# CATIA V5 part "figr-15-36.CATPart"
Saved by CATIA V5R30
Part number: Part1
Bounding box of the stored display mesh (mm): x -63.331 to 107.433, y -39.139 to 39.139, z 0 to 70.926
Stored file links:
  D:\PROJECTS\CATIA V56R 2020\Resources\Parts File\c15_catia_v5_6r2020_prt\figr-15-36.CATPart
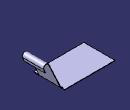
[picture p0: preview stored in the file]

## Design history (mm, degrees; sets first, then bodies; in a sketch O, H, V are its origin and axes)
SheetMetalParameters1: Thickness 1, BendRadius 2, KFactor 0.400515 {= log(min(100,max(20*SheetMetalParameters1.BendRadius,SheetMetalParameters1.Thickness)/SheetMetalParameters1.Thickness))/log(100)/2}, ReliefRadialLength 1, ReliefAxialLength 2, MinimumBendRadius 0
Body1 (main body)
  Sketch1 on xy-plane, origin (0, 0, 0), H (1, 0, 0), V (0, 1, 0)
    line L1 (-63.3311, 39.1393) -> (63.3311, 39.1393)
    line L2 (63.3311, 39.1393) -> (63.3311, -39.1393)
    line L3 (63.3311, -39.1393) -> (-63.3311, -39.1393)
    line L4 (-63.3311, -39.1393) -> (-63.3311, 39.1393)
    horizontal: L1 H, L3 H
    vertical: L2 V, L4 V
    symmetry: L4 L2 V, L1 L3 H
  Wall1: Thickness 1, Profile Sketch1
  d_NewWallOnEdge1: NewWallOnEdge_Edge edge [face of Wall1 | face of Wall1], NewWallOnEdge_Length 67, NewWallOnEdge_HeightLimitOffset 0, NewWallOnEdge_WidthOffset1 -16, NewWallOnEdge_WidthOffset2 -9, NewWallOnEdge_Angle 115, NewWallOnEdge_BendRadiusValue 2 {= SheetMetalParameters1.BendRadius}, NewWallOnEdge_BendTable SheetMetalParameters1, KFacteur 0.400515 {= log(min(100,max(20*d_NewWallOnEdge1.Radius,SheetMetalParameters1.Thickness)/SheetMetalParameters1.Thickness))/log(100)/2}
  Flange1: Angle 4, Length 10, Radius 6, KFacteur 0.5 {= log(min(100,max(20*Flange1.Radius,SheetMetalParameters1.Thickness)/SheetMetalParameters1.Thickness))/log(100)/2}, Guide edge [face of d_NewWallOnEdge1 | face of d_NewWallOnEdge1]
